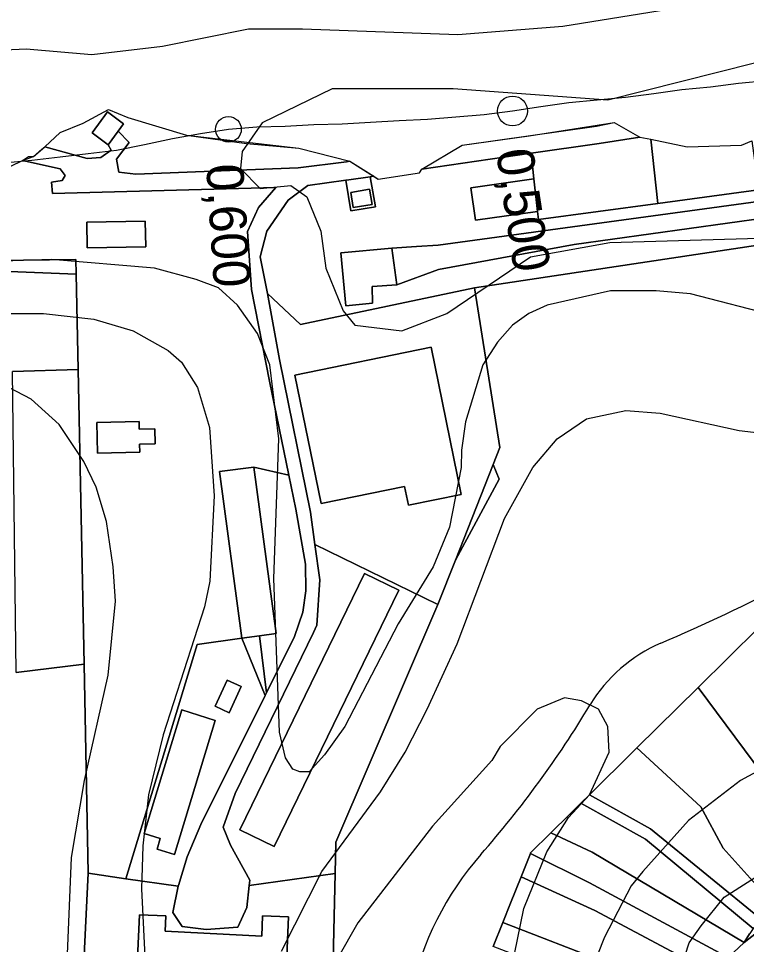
# Model space of a CAD drawing. Extents: x -510989 to -501240, y -1184665 to -1176098.
# Drawn here: x -505230.1 to -504974.5, y -1181152.6 to -1180827.3 of the extents above; entities that cross this region are included whole.
import ezdxf

# ---------------------------------------------------------------- set-up
doc = ezdxf.new("R2010")
doc.units = 0
for name, color, linetype in [('lesni_pozemek', 7, 'Continuous'), ('NAVRH_rozvodnice', 7, 'Continuous'), ('orna_puda', 7, 'Continuous'), ('ostatni_plocha_x_draha', 7, 'Continuous'), ('ostatni_plocha_x_jina_plocha', 7, 'Continuous'), ('ostatni_plocha_x_manipulacni_plocha', 7, 'Continuous'), ('ostatni_plocha_x_ostatni_komunikace', 7, 'Continuous'), ('ostatni_plocha_x_silnice', 7, 'Continuous'), ('popis', 7, 'Continuous'), ('trasovani_toku', 7, 'Continuous'), ('vrstevnice_01', 7, 'Continuous'), ('vrstevnice_02', 7, 'Continuous'), ('vrstevnice_03', 7, 'Continuous'), ('zahrada', 7, 'Continuous'), ('zastavena_plocha_a_nadvori', 7, 'Continuous')]:
    doc.layers.add(name, color=color, linetype=linetype)

msp = doc.modelspace()

# ---------------------------------------------------------------- linework, layer by layer
at = {"layer": 'lesni_pozemek'}
for points in [[(-505120.83, -1181208.41), (-505118.93, -1181127.61), (-505118.67, -1181116.61), (-505082.82, -1181033.14), (-505076.7, -1181017.64), (-505061.29, -1180989.17), (-505063.4, -1180984), (-505061.03, -1180977.99), (-505070, -1180922), (-504901.28, -1180896.57)], [(-505283.21, -1180914.2), (-505209.9, -1180917.09), (-505209.22, -1180950.61), (-505232.2, -1180951.3)], [(-504970.16, -1181041.3), (-504991.43, -1181062.3), (-505012.94, -1181083.54), (-505017.34, -1181087.88), (-505026.17, -1181096.59), (-505029.62, -1181100), (-505032.64, -1181102.98), (-505036.65, -1181106.94), (-505043.15, -1181113.36), (-505050.28, -1181120.4), (-505050.35, -1181120.59), (-505053.64, -1181128.85), (-505057.3, -1181138.06), (-505060.01, -1181144.87), (-505063.37, -1181153.3)], [(-505230.99, -1181057.06), (-505207.11, -1181054.09), (-505205.62, -1181127.59), (-505209.44, -1181204.5), (-505197.75, -1181205.02), (-505200.51, -1181214.37), (-505205.52, -1181251.84), (-505212.04, -1181251.64), (-505218.87, -1181277.63), (-505223.18, -1181277.13), (-505223.98, -1181294.03), (-505225.51, -1181293.85), (-505295.27, -1181285.31)]]:
    msp.add_lwpolyline(points, dxfattribs=at)
at = {"layer": 'NAVRH_rozvodnice'}
for centre, radius, start, end in [((-505269.53, -1180428.03), 673.1, 293.18985, 301.65308), ((-504983.29, -1181096.2), 53.8, 113.1899, 149.0092), ((-505339.08, -1180882.5), 361.23, 318.6825, 329.0092), ((-504986.74, -1181192.23), 107.88, 138.6825, 168.1112)]:
    msp.add_arc(centre, radius, start, end, dxfattribs=at)
at = {"layer": 'orna_puda'}
for points in [[(-504970.16, -1181041.3), (-504932.57, -1181091.77), (-504914.26, -1181117.19), (-504942.94, -1181127.57), (-504991.43, -1181062.3)], [(-504991.43, -1181062.3), (-504942.94, -1181127.57), (-504963.7, -1181139.89), (-504982.65, -1181118.78), (-504990.54, -1181104.29), (-505012.94, -1181083.54)], [(-505012.94, -1181083.54), (-504990.54, -1181104.29), (-504982.65, -1181118.78), (-504963.7, -1181139.89), (-504965.82, -1181142.13), (-504968.6, -1181144.24), (-505008.21, -1181112.02), (-505029.62, -1181100), (-505026.17, -1181096.59), (-505017.34, -1181087.88)], [(-505029.62, -1181100), (-505008.21, -1181112.02), (-504968.6, -1181144.24), (-504968.8, -1181144.39), (-504972.15, -1181147.01), (-505009.92, -1181115.56), (-505032.64, -1181102.98)], [(-505032.64, -1181102.98), (-505009.92, -1181115.56), (-504972.15, -1181147.01), (-504973.31, -1181148.76), (-504973.41, -1181148.91), (-504975.22, -1181151.9), (-505028.63, -1181120.2), (-505043.15, -1181113.36), (-505036.65, -1181106.94)], [(-505043.15, -1181113.36), (-505028.63, -1181120.2), (-504975.22, -1181151.9), (-504980.91, -1181157.21), (-505029.58, -1181130.91), (-505050.35, -1181120.59), (-505050.28, -1181120.4)], [(-505050.35, -1181120.59), (-505029.58, -1181130.91), (-504980.91, -1181157.21), (-504986.58, -1181162.51), (-505027.67, -1181140.67), (-505053.64, -1181128.85)], [(-505053.64, -1181128.85), (-505027.67, -1181140.67), (-504986.58, -1181162.51), (-504988.09, -1181163.92), (-504990.95, -1181167.81), (-504993.85, -1181171.75), (-505023.18, -1181159.17), (-505060.01, -1181144.87), (-505057.3, -1181138.06)], [(-505060.01, -1181144.87), (-505023.18, -1181159.17), (-504993.85, -1181171.75), (-505001.45, -1181177.13), (-505063.37, -1181153.3)]]:
    msp.add_lwpolyline(points, close=True, dxfattribs=at)
msp.add_lwpolyline([(-504964.53, -1181143.42), (-504975.22, -1181151.9), (-504973.41, -1181148.91)], dxfattribs=at)
at = {"layer": 'ostatni_plocha_x_draha'}
msp.add_lwpolyline([(-504903.2, -1180882.42), (-504902.38, -1180888.46), (-504947.79, -1180894.78), (-504967.64, -1180897.41), (-505034.97, -1180906.78), (-505082.62, -1180915.45), (-505097.23, -1180920.86), (-505099.02, -1180907.99), (-505090.37, -1180907.46), (-505082.68, -1180906.98), (-504949.75, -1180888.79)], close=True, dxfattribs=at)
at = {"layer": 'ostatni_plocha_x_jina_plocha'}
msp.add_lwpolyline([(-505071.27, -1180886.83), (-505049.13, -1180883.68), (-505047.86, -1180895.12), (-505069.65, -1180898.22)], close=True, dxfattribs=at)
at = {"layer": 'ostatni_plocha_x_manipulacni_plocha'}
for points in [[(-505198.51, -1180859.25), (-505191.75, -1180862.07), (-505171.13, -1180868.33), (-505150.09, -1180871.29), (-505131.66, -1180872.88), (-505113.75, -1180877.49), (-505114.91, -1180877.65), (-505131.86, -1180879.82), (-505188.86, -1180882.02), (-505194.91, -1180881.33), (-505195.71, -1180876.8), (-505191.3, -1180870.94), (-505195.15, -1180866.94), (-505193.24, -1180864.34), (-505198.85, -1180860.15), (-505204.27, -1180867.52), (-505198.67, -1180871.72), (-505197.58, -1180873.64), (-505201.25, -1180876.19), (-505205.98, -1180876.51), (-505220.9, -1180872.36), (-505215.46, -1180867.36), (-505207.42, -1180864.1)], [(-505011.85, -1180868.97), (-505008.04, -1180869.77), (-505005.53, -1180892.29), (-505047.55, -1180897.92), (-505047.86, -1180895.12), (-505049.13, -1180883.68), (-505050.13, -1180874.69), (-505026.23, -1180871.21)], [(-504976.25, -1180871.79), (-504972.62, -1180870.33), (-504970.29, -1180887.57), (-505005.53, -1180892.29), (-505008.04, -1180869.77), (-504995.29, -1180872.45)], [(-505114.12, -1180884.01), (-505106.58, -1180882.92), (-505104.79, -1180893.46), (-505113.37, -1180894.9), (-505115.18, -1180884.16)], [(-505113.44, -1180888.44), (-505112.55, -1180893.75), (-505105.94, -1180892.64), (-505106.84, -1180887.32)], [(-505206.1, -1180898.89), (-505205.96, -1180907.84), (-505185.37, -1180907.5), (-505185.67, -1180898.56)], [(-505283.65, -1180912.95), (-505210, -1180912), (-505209.9, -1180917.09), (-505283.21, -1180914.2)], [(-505070, -1180922), (-505061.03, -1180977.99), (-505063.4, -1180984), (-505076.7, -1181017.64), (-505082.82, -1181033.14), (-505126, -1181012.14), (-505127.62, -1181000.77), (-505138.43, -1180947.11), (-505142.62, -1180923.91), (-505131.09, -1180934.82)], [(-505085.24, -1180942.8), (-505133.05, -1180952.58), (-505123.8, -1180997.67), (-505094.53, -1180991.68), (-505093.15, -1180998.33), (-505074.64, -1180994.52)], [(-505202.63, -1180969.22), (-505202.36, -1180980.02), (-505187.5, -1180979.65), (-505187.57, -1180976.9), (-505182.07, -1180976.76), (-505182.21, -1180971.47), (-505187.7, -1180971.61), (-505187.77, -1180968.85)], [(-505063.4, -1180984), (-505061.29, -1180989.17), (-505076.7, -1181017.64)], [(-505159.52, -1180986.49), (-505147.43, -1180984.9), (-505139.59, -1181043.4), (-505145.54, -1181044.19), (-505151.74, -1181045.03)], [(-505147.43, -1180984.9), (-505135.21, -1180987.72), (-505132.77, -1180999.64), (-505129.33, -1181019.03), (-505129.25, -1181028.38), (-505130.24, -1181035.89), (-505133.15, -1181044.4), (-505143.02, -1181064.19), (-505145.54, -1181044.19), (-505139.59, -1181043.4)], [(-505124.24, -1181024.48), (-505126, -1181012.14), (-505082.82, -1181033.14), (-505118.67, -1181116.61), (-505118.93, -1181127.61), (-505149.13, -1181131.85), (-505148.93, -1181130), (-505155.69, -1181117.73), (-505158.19, -1181111.38), (-505154.04, -1181099.6), (-505126.53, -1181043.07), (-505125.37, -1181040.49)], [(-505096.6, -1181028.1), (-505108.66, -1181022.24), (-505152.41, -1181112.3), (-505140.31, -1181118.22)], [(-505167.35, -1181047.17), (-505151.74, -1181045.03), (-505143.52, -1181065.19), (-505166.09, -1181110.44), (-505170.85, -1181121.79), (-505173.95, -1181131.83), (-505174.02, -1181132.15), (-505192.39, -1181129.49)], [(-505145.54, -1181044.19), (-505143.02, -1181064.19), (-505143.52, -1181065.19), (-505151.74, -1181045.03)], [(-505156.83, -1181059.75), (-505161.1, -1181068.9), (-505156.15, -1181071.18), (-505151.87, -1181062.03)], [(-505161.08, -1181073.96), (-505172.73, -1181070.18), (-505185.94, -1181113.62), (-505180.31, -1181115.43), (-505181.4, -1181119.08), (-505175.35, -1181121.04)], [(-505205.62, -1181127.59), (-505192.39, -1181129.49), (-505174.02, -1181132.15), (-505175.87, -1181141.36), (-505172.64, -1181146.29), (-505164.24, -1181147.34), (-505153.08, -1181146.57), (-505149.96, -1181139.62), (-505149.13, -1181131.85), (-505118.93, -1181127.61), (-505120.83, -1181208.41), (-505122.43, -1181208.34), (-505173.74, -1181206.08), (-505197.75, -1181205.02), (-505209.44, -1181204.5)], [(-505187.63, -1181142.2), (-505189.91, -1181192.85), (-505137.56, -1181195.16), (-505135.3, -1181142.88), (-505144.39, -1181142.59), (-505144.64, -1181149.69), (-505178.6, -1181147.98), (-505178.35, -1181142.55)]]:
    msp.add_lwpolyline(points, close=True, dxfattribs=at)
for points in [[(-505245.25, -1180885.12), (-505228.75, -1180877.16), (-505215.51, -1180880.16), (-505213.79, -1180882.46), (-505214.78, -1180884.2), (-505218.56, -1180884.87), (-505218.17, -1180888.8), (-505139.79, -1180886.72), (-505145.82, -1180893.73), (-505149.73, -1180902.21), (-505148.27, -1180922.57), (-505141.98, -1180954.72), (-505135.21, -1180987.72), (-505147.43, -1180984.9), (-505159.52, -1180986.49), (-505151.74, -1181045.03), (-505167.35, -1181047.17), (-505192.39, -1181129.49), (-505205.62, -1181127.59), (-505207.11, -1181054.09), (-505209.22, -1180950.61), (-505209.9, -1180917.09), (-505210, -1180912), (-505283.65, -1180912.95)], [(-504901.28, -1180896.57), (-505070, -1180922), (-505131.09, -1180934.82), (-505142.62, -1180923.91), (-505145.19, -1180911), (-505142.94, -1180901.99), (-505135.38, -1180891.19), (-505128.46, -1180886.01), (-505115.18, -1180884.16), (-505113.37, -1180894.9), (-505104.79, -1180893.46), (-505106.58, -1180882.92), (-505105.3, -1180882.73), (-505103.84, -1180883.77), (-505089.32, -1180881.6), (-505088.42, -1180880.27), (-505050.13, -1180874.69), (-505049.13, -1180883.68), (-505071.27, -1180886.83), (-505069.65, -1180898.22), (-505047.86, -1180895.12), (-505047.55, -1180897.92), (-505005.53, -1180892.29), (-504970.29, -1180887.57)], [(-504949.75, -1180888.79), (-505082.68, -1180906.98), (-505090.37, -1180907.46), (-505099.02, -1180907.99), (-505116.94, -1180909.67), (-505115.2, -1180928.24), (-505105.74, -1180927.35), (-505105.96, -1180921.47), (-505097.23, -1180920.86), (-505082.62, -1180915.45), (-505034.97, -1180906.78), (-504967.64, -1180897.41)]]:
    msp.add_lwpolyline(points, dxfattribs=at)
at = {"layer": 'ostatni_plocha_x_ostatni_komunikace'}
for points in [[(-505020.87, -1180863.81), (-505011.85, -1180868.97), (-505026.23, -1180871.21), (-505050.13, -1180874.69), (-505088.42, -1180880.27), (-505074.34, -1180871.87), (-505027.18, -1180865.14)], [(-505195.15, -1180866.94), (-505191.3, -1180870.94), (-505195.71, -1180876.8), (-505194.91, -1180881.33), (-505188.86, -1180882.02), (-505131.86, -1180879.82), (-505114.91, -1180877.65), (-505113.75, -1180877.49), (-505105.3, -1180882.73), (-505106.58, -1180882.92), (-505114.12, -1180884.01), (-505115.18, -1180884.16), (-505128.46, -1180886.01), (-505135.38, -1180891.19), (-505142.94, -1180901.99), (-505145.19, -1180911), (-505142.62, -1180923.91), (-505138.43, -1180947.11), (-505127.62, -1181000.77), (-505126, -1181012.14), (-505124.24, -1181024.48), (-505125.37, -1181040.49), (-505126.53, -1181043.07), (-505154.04, -1181099.6), (-505158.19, -1181111.38), (-505155.69, -1181117.73), (-505148.93, -1181130), (-505149.13, -1181131.85), (-505149.96, -1181139.62), (-505153.08, -1181146.57), (-505164.24, -1181147.34), (-505172.64, -1181146.29), (-505175.87, -1181141.36), (-505174.02, -1181132.15), (-505173.95, -1181131.83), (-505170.85, -1181121.79), (-505166.09, -1181110.44), (-505143.52, -1181065.19), (-505143.02, -1181064.19), (-505133.15, -1181044.4), (-505130.24, -1181035.89), (-505129.25, -1181028.38), (-505129.33, -1181019.03), (-505132.77, -1180999.64), (-505135.21, -1180987.72), (-505141.98, -1180954.72), (-505148.27, -1180922.57), (-505149.73, -1180902.21), (-505145.82, -1180893.73), (-505139.79, -1180886.72), (-505218.17, -1180888.8), (-505218.56, -1180884.87), (-505214.78, -1180884.2), (-505213.79, -1180882.46), (-505215.51, -1180880.16), (-505228.75, -1180877.16), (-505226.57, -1180875.83), (-505224.82, -1180875.83), (-505221.91, -1180873.21), (-505220.9, -1180872.36), (-505205.98, -1180876.51), (-505201.25, -1180876.19), (-505197.58, -1180873.64), (-505198.67, -1180871.72)]]:
    msp.add_lwpolyline(points, close=True, dxfattribs=at)
at = {"layer": 'ostatni_plocha_x_silnice'}
msp.add_lwpolyline([(-504980.91, -1181157.21), (-504975.22, -1181151.9), (-504964.53, -1181143.42)], dxfattribs=at)
at = {"layer": 'popis'}
msp.add_lwpolyline([(-505245.25, -1180885.12), (-505228.75, -1180877.16), (-505224.82, -1180875.83), (-505220.9, -1180872.36), (-505215.46, -1180867.36), (-505207.42, -1180864.1), (-505198.51, -1180859.25), (-505191.75, -1180862.07), (-505171.13, -1180868.33), (-505131.66, -1180872.88), (-505113.75, -1180877.49), (-505103.84, -1180883.77), (-505089.32, -1180881.6), (-505088.42, -1180880.27), (-505074.34, -1180871.87), (-505050.76, -1180868.51), (-505020.87, -1180863.81), (-505011.85, -1180868.97), (-505008.04, -1180869.77), (-504995.29, -1180872.45), (-504976.25, -1180871.79), (-504972.62, -1180870.33)], dxfattribs=at)
at = {"layer": 'trasovani_toku'}
for p, q in [((-504977.23, -1180850.18), (-504987.14, -1180851.5)), ((-504967.28, -1180849.19), (-504977.23, -1180850.18)), ((-505007.01, -1180853.78), (-505016.92, -1180855.06)), ((-504997.1, -1180852.41), (-505007.01, -1180853.78)), ((-504987.14, -1180851.5), (-504997.1, -1180852.41)), ((-505036.83, -1180856.95), (-505046.73, -1180858.41)), ((-505026.88, -1180856.02), (-505036.83, -1180856.95)), ((-505016.92, -1180855.06), (-505026.88, -1180856.02)), ((-505056.62, -1180859.83), (-505066.54, -1180861.13)), ((-505046.73, -1180858.41), (-505056.62, -1180859.83)), ((-505106.44, -1180863.9), (-505116.43, -1180864.41)), ((-505096.46, -1180863.3), (-505106.44, -1180863.9)), ((-505086.47, -1180862.8), (-505096.46, -1180863.3)), ((-505076.5, -1180861.98), (-505086.47, -1180862.8)), ((-505066.54, -1180861.13), (-505076.5, -1180861.98)), ((-505156.38, -1180866.27), (-505166.25, -1180867.85)), ((-505146.4, -1180865.56), (-505156.38, -1180866.27)), ((-505136.41, -1180865.24), (-505146.4, -1180865.56)), ((-505126.42, -1180864.71), (-505136.41, -1180865.24)), ((-505116.43, -1180864.41), (-505126.42, -1180864.71)), ((-505176.09, -1180869.62), (-505185.86, -1180871.76)), ((-505166.25, -1180867.85), (-505176.09, -1180869.62)), ((-505195.66, -1180873.76), (-505205.6, -1180874.9)), ((-505185.86, -1180871.76), (-505195.66, -1180873.76)), ((-505225.46, -1180877.2), (-505235.42, -1180878.16)), ((-505215.53, -1180876.01), (-505225.46, -1180877.2)), ((-505205.6, -1180874.9), (-505215.53, -1180876.01))]:
    msp.add_line(p, q, dxfattribs=at)
for centre, radius in [((-505056.62, -1180859.83), 5.25), ((-505156.38, -1180866.27), 4.5)]:
    msp.add_circle(centre, radius, dxfattribs=at)
at = {"layer": 'vrstevnice_01'}
for points in [[(-504971.69, -1180843), (-505023.09, -1180856), (-505077.5, -1180852), (-505120, -1180852), (-505144.5, -1180864), (-505151.59, -1180874), (-505152.19, -1180880), (-505145.19, -1180887), (-505134.5, -1180886), (-505128.81, -1180890), (-505123.91, -1180902), (-505122.19, -1180915), (-505116.09, -1180930), (-505112, -1180935), (-505095.5, -1180937), (-505079.69, -1180931), (-505050.31, -1180911), (-505022.5, -1180906), (-504953.91, -1180904)], [(-505256.31, -1180931), (-505221.31, -1180931), (-505203.69, -1180933), (-505189.81, -1180937), (-505177.59, -1180944), (-505172.91, -1180948), (-505167.31, -1180957), (-505163, -1180971), (-505161.41, -1180995), (-505162.91, -1181025), (-505164.81, -1181034), (-505179.31, -1181079), (-505184.41, -1181100), (-505186.41, -1181118), (-505186.91, -1181133), (-505184.41, -1181183)], [(-505137.81, -1181155), (-505123.59, -1181127), (-505103, -1181099), (-505094.31, -1181085), (-505086.59, -1181070), (-505076.09, -1181047), (-505059.41, -1181003), (-505049.5, -1180985), (-505040.91, -1180975), (-505030.69, -1180968), (-505016.81, -1180965), (-505004.81, -1180966), (-504977, -1180972), (-504951.81, -1180975)], [(-504932.31, -1181071), (-504976.59, -1181095), (-504994.81, -1181109), (-505010.81, -1181127), (-505014.91, -1181132), (-505024.31, -1181150), (-505029.5, -1181163)]]:
    msp.add_lwpolyline(points, dxfattribs=at)
at = {"layer": 'vrstevnice_02'}
for points in [[(-505250.09, -1180839), (-505227.41, -1180838), (-505204.41, -1180840), (-505179.5, -1180837), (-505149.31, -1180831), (-505130.41, -1180831), (-505075.81, -1180833), (-505039, -1180830), (-505001.81, -1180824), (-504973.69, -1180817), (-504959.69, -1180812), (-504938.09, -1180803), (-504926.09, -1180797), (-504911.69, -1180787), (-504899.69, -1180774), (-504895.81, -1180768), (-504891.19, -1180759), (-504888.19, -1180745)], [(-504963.31, -1180932), (-504994.09, -1180924), (-505006.19, -1180923), (-505022.19, -1180923), (-505044.5, -1180928), (-505050.91, -1180931), (-505056.59, -1180935), (-505061.91, -1180941), (-505067.09, -1180949), (-505073.09, -1180969), (-505074.59, -1180979), (-505074.69, -1180985), (-505078.81, -1181006), (-505084.5, -1181020), (-505096.81, -1181040), (-505115.5, -1181076), (-505122.69, -1181086), (-505128, -1181092), (-505131.31, -1181092), (-505133.81, -1181091), (-505136.31, -1181087), (-505138.5, -1181078), (-505140.41, -1181024), (-505138.69, -1180975), (-505141.81, -1180949), (-505146.19, -1180938), (-505153.19, -1180928), (-505159.91, -1180922), (-505167.69, -1180919), (-505182.31, -1180915), (-505218.59, -1180912), (-505249.19, -1180913)], [(-505231.31, -1181291), (-505215.91, -1181244), (-505211.81, -1181224), (-505210.5, -1181211), (-505210.19, -1181189), (-505212.91, -1181156), (-505211.5, -1181122), (-505207, -1181095), (-505198.59, -1181058), (-505196.09, -1181032), (-505196.91, -1181020), (-505199.19, -1181004), (-505202.81, -1180992), (-505207.19, -1180983), (-505215.81, -1180970), (-505225.69, -1180961), (-505241.19, -1180953)], [(-504997.5, -1181161), (-504994.59, -1181152), (-504990.31, -1181146), (-504982.31, -1181136), (-504963.59, -1181124)]]:
    msp.add_lwpolyline(points, dxfattribs=at)
at = {"layer": 'vrstevnice_03'}
msp.add_lwpolyline([(-505053.19, -1181221), (-505056.19, -1181206), (-505057, -1181194), (-505055.91, -1181156), (-505052.69, -1181140), (-505044.59, -1181120), (-505036.91, -1181108), (-505029.59, -1181100), (-505022.69, -1181085), (-505023.19, -1181076), (-505026.41, -1181070), (-505032.41, -1181067), (-505038.41, -1181066), (-505048, -1181070), (-505060.91, -1181083), (-505063.91, -1181088), (-505084.69, -1181111), (-505110.91, -1181145), (-505125.19, -1181170)], dxfattribs=at)
at = {"layer": 'zahrada'}
msp.add_lwpolyline([(-505209.22, -1180950.61), (-505207.11, -1181054.09), (-505230.99, -1181057.06), (-505232.2, -1180951.3)], close=True, dxfattribs=at)
at = {"layer": 'zastavena_plocha_a_nadvori'}
for points in [[(-505198.85, -1180860.15), (-505193.24, -1180864.34), (-505195.15, -1180866.94), (-505198.67, -1180871.72), (-505204.27, -1180867.52)], [(-505113.44, -1180888.44), (-505106.84, -1180887.32), (-505105.94, -1180892.64), (-505112.55, -1180893.75)], [(-505206.1, -1180898.89), (-505185.67, -1180898.56), (-505185.37, -1180907.5), (-505205.96, -1180907.84)], [(-505099.02, -1180907.99), (-505097.23, -1180920.86), (-505105.96, -1180921.47), (-505105.74, -1180927.35), (-505115.2, -1180928.24), (-505116.94, -1180909.67)], [(-505085.24, -1180942.8), (-505074.64, -1180994.52), (-505093.15, -1180998.33), (-505094.53, -1180991.68), (-505123.8, -1180997.67), (-505133.05, -1180952.58)], [(-505202.63, -1180969.22), (-505187.77, -1180968.85), (-505187.7, -1180971.61), (-505182.21, -1180971.47), (-505182.07, -1180976.76), (-505187.57, -1180976.9), (-505187.5, -1180979.65), (-505202.36, -1180980.02)], [(-505096.6, -1181028.1), (-505140.31, -1181118.22), (-505152.41, -1181112.3), (-505108.66, -1181022.24)], [(-505156.83, -1181059.75), (-505151.87, -1181062.03), (-505156.15, -1181071.18), (-505161.1, -1181068.9)], [(-505161.08, -1181073.96), (-505175.35, -1181121.04), (-505181.4, -1181119.08), (-505180.31, -1181115.43), (-505185.94, -1181113.62), (-505172.73, -1181070.18)], [(-505187.63, -1181142.2), (-505178.35, -1181142.55), (-505178.6, -1181147.98), (-505144.64, -1181149.69), (-505144.39, -1181142.59), (-505135.3, -1181142.88), (-505137.56, -1181195.16), (-505189.91, -1181192.85)]]:
    msp.add_lwpolyline(points, close=True, dxfattribs=at)

# ---------------------------------------------------------------- texts
at = {"layer": 'trasovani_toku'}
for s, rotation, p in [('0,500', 278.5382, (-505062.44, -1180873.99)), ('0,600', 273.6604, (-505164.24, -1180878.76))]:
    msp.add_text(s, height=13, rotation=rotation, dxfattribs=at).set_placement(p)

doc.saveas('drawing.dxf')
